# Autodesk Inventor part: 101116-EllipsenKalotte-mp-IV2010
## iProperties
Created: 2010-11
Part Number: 101116-EllipsenKalotte-mp-IV2010
Document SubType Name: Modeling
Designer: MP
Density: 1 g/cm^3
Author: MP
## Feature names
1. Extrusion1
2. Extrusion2
3. Rundung1 [Fillet]
